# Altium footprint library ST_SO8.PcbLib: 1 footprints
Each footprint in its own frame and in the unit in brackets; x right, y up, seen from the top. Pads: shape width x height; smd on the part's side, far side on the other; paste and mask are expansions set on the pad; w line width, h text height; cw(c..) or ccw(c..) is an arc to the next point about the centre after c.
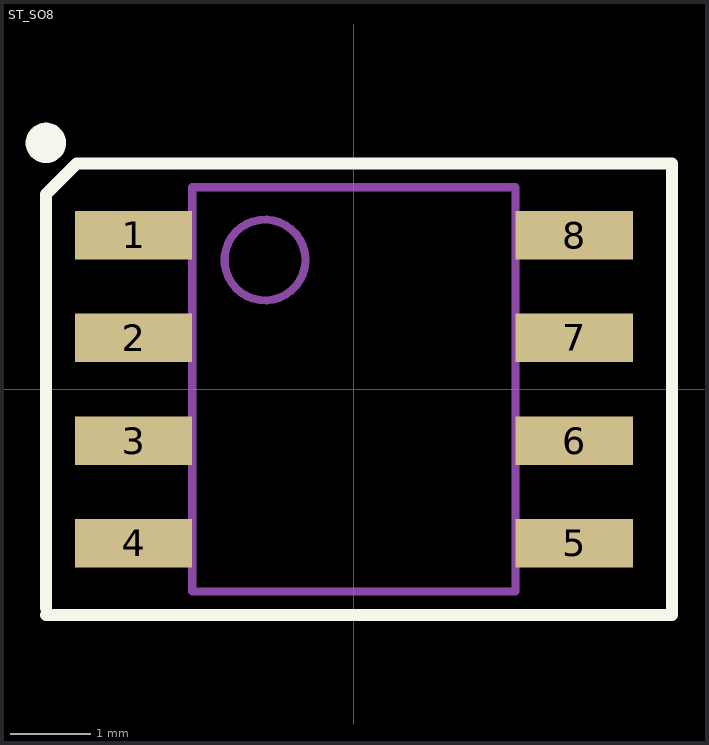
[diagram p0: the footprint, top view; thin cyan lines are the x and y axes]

## ST_SO8 [mm]
height 1.75
pads (8):
  rect 1.45x0.6 smd: 1(-2.725,1.905) 2(-2.725,0.635) 3(-2.725,-0.635) 4(-2.725,-1.905) 5(2.725,-1.905) 6(2.725,-0.635) 7(2.725,0.635) 8(2.725,1.905)
Top Overlay:
  circle w0.25: c-3.81,3.048 r0.125
  lines w0.15: -3.81,-2.794 3.937,-2.794 3.937,2.794 -3.429,2.794 -3.81,2.413 -3.81,-2.706
Mechanical 13:
  circle w0.1: c-1.1,1.6 r0.5
  lines w0.1: -2,-2.5 -2,2.5 2,2.5 2,-2.5 -2,-2.5
3D body "SO8127P600-8N-PEP01.step": height 1.75, standoff 0, extent -3,-2.5 3,2.5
